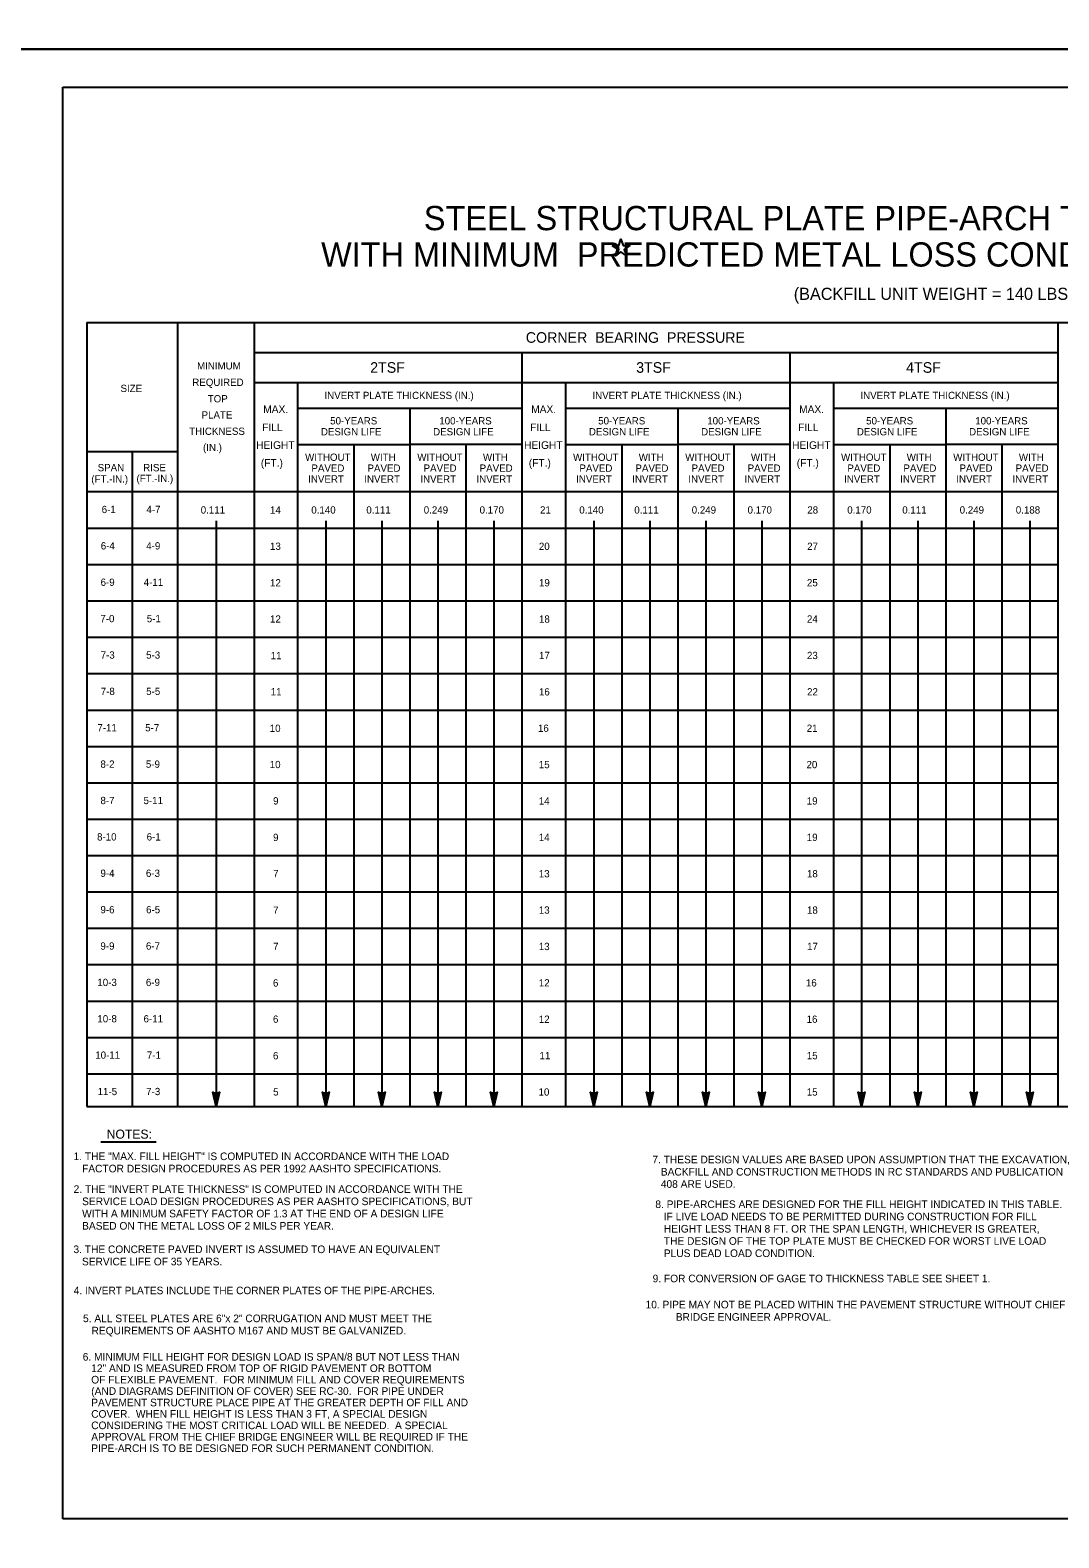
# Model space of a CAD drawing. Extents: x 591 to 2288, y -189 to 2187.
# Drawn here: x 1459 to 1865, y 1007 to 1601 of the extents above; entities that cross this region are included whole.
import ezdxf

# ---------------------------------------------------------------- set-up
doc = ezdxf.new("R2010")
doc.units = 0
for name, color, linetype in [('1', 7, 'Continuous'), ('2', 7, 'Continuous'), ('PLT-BNDY', 7, 'Continuous')]:
    doc.layers.add(name, color=color, linetype=linetype)

msp = doc.modelspace()

# ---------------------------------------------------------------- linework, layer by layer
at = {"layer": '1'}
for p, q in [((1481.73, 1485.59), (1481.73, 1176.64)), ((1481.73, 1485.59), (2247.72, 1485.59)), ((1517.56, 1485.59), (1517.56, 1176.64)), ((1547.65, 1485.59), (1547.65, 1176.64)), ((1864.37, 1485.59), (1864.37, 1176.64)), ((1547.65, 1473.72), (1864.37, 1473.72)), ((1653.22, 1473.72), (1653.22, 1176.64)), ((1758.8, 1473.72), (1758.8, 1176.64)), ((1547.65, 1461.85), (1653.22, 1461.85)), ((1564.84, 1461.85), (1564.84, 1176.64)), ((1653.22, 1461.85), (1758.8, 1461.85)), ((1670.41, 1461.85), (1670.41, 1176.64)), ((1758.8, 1461.85), (1864.37, 1461.85)), ((1775.98, 1461.85), (1775.98, 1176.64)), ((1564.84, 1451.82), (1653.22, 1451.82)), ((1609.03, 1451.82), (1609.03, 1176.64)), ((1670.41, 1451.82), (1758.8, 1451.82)), ((1714.6, 1451.82), (1714.6, 1176.64)), ((1775.98, 1451.82), (1864.37, 1451.82)), ((1820.17, 1451.82), (1820.17, 1176.64)), ((1564.84, 1437.48), (1609.03, 1437.48)), ((1586.94, 1437.48), (1586.94, 1176.64)), ((1653.22, 1437.48), (1609.03, 1437.48)), ((1631.13, 1437.48), (1631.13, 1176.64)), ((1670.41, 1437.48), (1714.6, 1437.48)), ((1692.51, 1437.48), (1692.51, 1176.64)), ((1758.8, 1437.48), (1714.6, 1437.48)), ((1736.7, 1437.48), (1736.7, 1176.64)), ((1775.98, 1437.48), (1820.17, 1437.48)), ((1798.08, 1437.48), (1798.08, 1176.64)), ((1864.37, 1437.48), (1820.17, 1437.48)), ((1842.27, 1437.48), (1842.27, 1176.64)), ((1517.56, 1434.62), (1481.73, 1434.62)), ((1499.64, 1434.62), (1499.64, 1176.64)), ((1864.37, 1418.85), (1481.73, 1418.85)), ((1481.73, 1404.52), (1864.37, 1404.52)), ((1532.75, 1407.43), (1532.75, 1176.64)), ((1575.88, 1407.43), (1575.88, 1176.64)), ((1597.99, 1407.43), (1597.99, 1176.64)), ((1620.08, 1407.43), (1620.08, 1176.64)), ((1642.18, 1407.43), (1642.18, 1176.64)), ((1681.46, 1407.43), (1681.46, 1176.64)), ((1703.56, 1407.43), (1703.56, 1176.64)), ((1725.65, 1407.43), (1725.65, 1176.64)), ((1747.75, 1407.43), (1747.75, 1176.64)), ((1787.03, 1407.43), (1787.03, 1176.64)), ((1809.13, 1407.43), (1809.13, 1176.64)), ((1831.22, 1407.43), (1831.22, 1176.64)), ((1853.32, 1407.43), (1853.32, 1176.64)), ((1481.73, 1390.19), (1864.37, 1390.19)), ((1481.73, 1375.86), (1864.37, 1375.86)), ((1481.73, 1361.52), (1864.37, 1361.52)), ((1481.73, 1347.19), (1864.37, 1347.19)), ((1481.73, 1332.86), (1864.37, 1332.86)), ((1481.73, 1318.53), (1864.37, 1318.53)), ((1481.73, 1304.2), (1864.37, 1304.2)), ((1481.73, 1289.86), (1864.37, 1289.86)), ((1481.73, 1275.53), (1864.37, 1275.53)), ((1481.73, 1261.2), (1864.37, 1261.2)), ((1481.73, 1246.87), (1864.37, 1246.87)), ((1481.73, 1232.54), (1864.37, 1232.54)), ((1481.73, 1218.2), (1864.37, 1218.2)), ((1481.73, 1203.87), (1864.37, 1203.87)), ((1481.73, 1189.54), (1864.37, 1189.54)), ((1481.73, 1176.64), (1864.37, 1176.64)), ((1864.37, 1176.64), (2247.72, 1176.64)), ((1487.31, 1162.71), (1509.1, 1162.71))]:
    msp.add_line(p, q, dxfattribs=at)
for points in [[(1533.72, 1182.06), (1533.16, 1181.86), (1532.75, 1176.64), (1533.72, 1182.06), (1534.07, 1182.34), (1532.75, 1176.64), (1532.37, 1181.86), (1531.81, 1182.05), (1532.75, 1176.64), (1531.44, 1182.34), (1531.81, 1182.05)], [(1576.86, 1182.06), (1576.3, 1181.86), (1575.88, 1176.64), (1576.86, 1182.06), (1577.21, 1182.34), (1575.88, 1176.64), (1575.51, 1181.86), (1574.95, 1182.05), (1575.88, 1176.64), (1574.58, 1182.34), (1574.95, 1182.05)], [(1598.97, 1182.06), (1598.4, 1181.86), (1597.99, 1176.64), (1598.97, 1182.06), (1599.31, 1182.34), (1597.99, 1176.64), (1597.61, 1181.86), (1597.05, 1182.05), (1597.99, 1176.64), (1596.68, 1182.34), (1597.05, 1182.05)], [(1621.06, 1182.06), (1620.5, 1181.86), (1620.08, 1176.64), (1621.06, 1182.06), (1621.4, 1182.34), (1620.08, 1176.64), (1619.71, 1181.86), (1619.15, 1182.05), (1620.08, 1176.64), (1618.78, 1182.34), (1619.15, 1182.05)], [(1643.16, 1182.06), (1642.59, 1181.86), (1642.18, 1176.64), (1643.16, 1182.06), (1643.5, 1182.34), (1642.18, 1176.64), (1641.81, 1181.86), (1641.25, 1182.05), (1642.18, 1176.64), (1640.87, 1182.34), (1641.25, 1182.05)], [(1682.44, 1182.06), (1681.87, 1181.86), (1681.46, 1176.64), (1682.44, 1182.06), (1682.78, 1182.34), (1681.46, 1176.64), (1681.08, 1181.86), (1680.53, 1182.05), (1681.46, 1176.64), (1680.15, 1182.34), (1680.53, 1182.05)], [(1704.54, 1182.06), (1703.97, 1181.86), (1703.56, 1176.64), (1704.54, 1182.06), (1704.88, 1182.34), (1703.56, 1176.64), (1703.18, 1181.86), (1702.62, 1182.05), (1703.56, 1176.64), (1702.25, 1182.34), (1702.62, 1182.05)], [(1726.63, 1182.06), (1726.07, 1181.86), (1725.65, 1176.64), (1726.63, 1182.06), (1726.97, 1182.34), (1725.65, 1176.64), (1725.28, 1181.86), (1724.72, 1182.05), (1725.65, 1176.64), (1724.35, 1182.34), (1724.72, 1182.05)], [(1748.73, 1182.06), (1748.17, 1181.86), (1747.75, 1176.64), (1748.73, 1182.06), (1749.07, 1182.34), (1747.75, 1176.64), (1747.38, 1181.86), (1746.82, 1182.05), (1747.75, 1176.64), (1746.45, 1182.34), (1746.82, 1182.05)], [(1788.01, 1182.06), (1787.44, 1181.86), (1787.03, 1176.64), (1788.01, 1182.06), (1788.35, 1182.34), (1787.03, 1176.64), (1786.65, 1181.86), (1786.1, 1182.05), (1787.03, 1176.64), (1785.72, 1182.34), (1786.1, 1182.05)], [(1810.11, 1182.06), (1809.54, 1181.86), (1809.13, 1176.64), (1810.11, 1182.06), (1810.45, 1182.34), (1809.13, 1176.64), (1808.76, 1181.86), (1808.19, 1182.05), (1809.13, 1176.64), (1807.82, 1182.34), (1808.19, 1182.05)], [(1832.2, 1182.06), (1831.64, 1181.86), (1831.22, 1176.64), (1832.2, 1182.06), (1832.55, 1182.34), (1831.22, 1176.64), (1830.85, 1181.86), (1830.29, 1182.05), (1831.22, 1176.64), (1829.92, 1182.34), (1830.29, 1182.05)], [(1854.3, 1182.06), (1853.74, 1181.86), (1853.32, 1176.64), (1854.3, 1182.06), (1854.64, 1182.34), (1853.32, 1176.64), (1852.95, 1181.86), (1852.39, 1182.05), (1853.32, 1176.64), (1852.02, 1182.34), (1852.39, 1182.05)]]:
    msp.add_lwpolyline(points, dxfattribs=at)
at = {"layer": '2'}
for p, q in [((1472.34, 1014.21), (1472.34, 1578.21)), ((1472.34, 1578.21), (2258.34, 1578.21)), ((1692.07, 1514.69), (1692.07, 1514.69)), ((2258.34, 1014.21), (1472.34, 1014.21))]:
    msp.add_line(p, q, dxfattribs=at)
msp.add_lwpolyline([(1688.77, 1515.92), (1691.41, 1515.89), (1692.22, 1518.42), (1693.02, 1515.89), (1695.67, 1515.92), (1693.51, 1514.35), (1694.35, 1511.85), (1692.2, 1513.41), (1690.09, 1511.85), (1690.9, 1514.36), (1688.77, 1515.92)], dxfattribs=at)
at = {"layer": 'PLT-BNDY'}
for points in [[(1432.34, 2187.21), (2273.34, 2187.21), (2273.34, 1593.21), (1432.34, 1593.21)], [(1432.34, 1593.21), (2273.34, 1593.21), (2273.34, 999.21), (1432.34, 999.21)]]:
    msp.add_lwpolyline(points, close=True, dxfattribs=at)

# ---------------------------------------------------------------- texts
at = {"layer": '1'}
for s, height, p in [('STEEL STRUCTURAL PLATE PIPE-ARCH THICKNESS REQUIREMENTS', 9.5546, (1614.55, 1521.89)), ('WITH MINIMUM  PREDICTED METAL LOSS CONDITION (18" CORNER RADIUS)', 9.5546, (1574.08, 1507.57)), ('(BACKFILL UNIT WEIGHT = 140 LBS. PER CU. FT.)', 4.7773, (1760.29, 1494.45)), ('CORNER  BEARING  PRESSURE', 4.1801, (1654.73, 1477.53)), ('MINIMUM', 2.866, (1525.2, 1467.03)), ('2TSF', 4.18, (1593.42, 1465.72)), ('3TSF', 4.18, (1698.21, 1465.72)), ('4TSF', 4.18, (1804.57, 1465.72)), ('REQUIRED', 2.866, (1523.33, 1460.55)), ('SIZE', 2.866, (1495.05, 1458.15)), ('TOP', 2.866, (1529.42, 1454.07)), ('INVERT PLATE THICKNESS (IN.)', 2.8664, (1575.41, 1455.37)), ('INVERT PLATE THICKNESS (IN.)', 2.8664, (1680.98, 1455.37)), ('INVERT PLATE THICKNESS (IN.)', 2.8664, (1786.55, 1455.37)), ('PLATE', 2.866, (1526.99, 1447.67)), ('THICKNESS', 2.866, (1522.12, 1441.26)), ('DESIGN LIFE', 2.8664, (1574.01, 1441.07)), ('50-YEARS', 2.866, (1577.66, 1445.37)), ('DESIGN LIFE', 2.8664, (1618.21, 1441.07)), ('100-YEARS', 2.866, (1620.64, 1445.37)), ('DESIGN LIFE', 2.8664, (1679.58, 1441.07)), ('50-YEARS', 2.866, (1683.24, 1445.37)), ('DESIGN LIFE', 2.8664, (1723.78, 1441.07)), ('100-YEARS', 2.866, (1726.21, 1445.37)), ('DESIGN LIFE', 2.8664, (1785.15, 1441.07)), ('50-YEARS', 2.866, (1788.81, 1445.37)), ('DESIGN LIFE', 2.8664, (1829.35, 1441.07)), ('100-YEARS', 2.866, (1831.78, 1445.37)), ('(IN.)', 2.866, (1527.56, 1434.86)), ('WITHOUT', 2.866, (1567.78, 1431.03)), ('WITH', 2.866, (1593.65, 1431.03)), ('WITHOUT', 2.866, (1611.97, 1431.03)), ('WITH', 2.866, (1637.84, 1431.03)), ('WITHOUT', 2.866, (1673.35, 1431.03)), ('WITH', 2.866, (1699.22, 1431.03)), ('WITHOUT', 2.866, (1717.54, 1431.03)), ('WITH', 2.866, (1743.41, 1431.03)), ('WITHOUT', 2.866, (1778.92, 1431.03)), ('WITH', 2.866, (1804.79, 1431.03)), ('WITHOUT', 2.866, (1823.11, 1431.03)), ('WITH', 2.866, (1848.98, 1431.03)), ('SPAN', 2.866, (1486.06, 1426.92)), ('(FT.-IN.)', 2.866, (1501.35, 1422.65)), ('RISE', 2.866, (1503.99, 1426.92)), ('PAVED', 2.866, (1570.27, 1426.73)), ('PAVED', 2.866, (1592.36, 1426.73)), ('PAVED', 2.866, (1614.46, 1426.73)), ('PAVED', 2.866, (1636.55, 1426.73)), ('PAVED', 2.866, (1675.84, 1426.73)), ('PAVED', 2.866, (1697.93, 1426.73)), ('PAVED', 2.866, (1720.03, 1426.73)), ('PAVED', 2.866, (1742.12, 1426.73)), ('PAVED', 2.866, (1781.41, 1426.73)), ('PAVED', 2.866, (1803.5, 1426.73)), ('PAVED', 2.866, (1825.6, 1426.73)), ('PAVED', 2.866, (1847.7, 1426.73)), ('(FT.-IN.)', 2.866, (1483.55, 1422.45)), ('INVERT', 2.866, (1569, 1422.44)), ('INVERT', 2.866, (1591.09, 1422.44)), ('INVERT', 2.866, (1613.19, 1422.44)), ('INVERT', 2.866, (1635.29, 1422.44)), ('INVERT', 2.866, (1674.57, 1422.44)), ('INVERT', 2.866, (1696.66, 1422.44)), ('INVERT', 2.866, (1718.76, 1422.44)), ('INVERT', 2.866, (1740.86, 1422.44)), ('INVERT', 2.866, (1780.14, 1422.44)), ('INVERT', 2.866, (1802.23, 1422.44)), ('INVERT', 2.866, (1824.33, 1422.44)), ('INVERT', 2.866, (1846.43, 1422.44)), ('6-1', 2.866, (1487.63, 1410.44)), ('4-7', 2.866, (1505.26, 1410.44)), ('0.111', 2.866, (1526.66, 1410.25)), ('14', 2.866, (1553.95, 1410.21)), ('0.140', 2.866, (1570.22, 1410.25)), ('0.111', 2.866, (1591.9, 1410.25)), ('0.249', 2.866, (1614.52, 1410.25)), ('0.170', 2.866, (1636.52, 1410.25)), ('21', 2.866, (1660.33, 1410.25)), ('0.140', 2.866, (1675.79, 1410.25)), ('0.111', 2.866, (1697.47, 1410.25)), ('0.249', 2.866, (1720.09, 1410.25)), ('0.170', 2.866, (1742.09, 1410.25)), ('28', 2.866, (1765.62, 1410.25)), ('0.170', 2.866, (1781.36, 1410.25)), ('0.111', 2.866, (1803.04, 1410.25)), ('0.249', 2.866, (1825.66, 1410.25)), ('0.188', 2.866, (1847.77, 1410.25)), ('6-4', 2.866, (1487.28, 1396.11)), ('4-9', 2.866, (1505.19, 1396.11)), ('13', 2.866, (1553.95, 1395.96)), ('20', 2.866, (1659.88, 1395.92)), ('27', 2.866, (1765.56, 1395.92)), ('6-9', 2.866, (1487.21, 1381.77)), ('4-11', 2.866, (1504.19, 1381.77)), ('12', 2.866, (1553.95, 1381.55)), ('19', 2.866, (1659.91, 1381.59)), ('25', 2.866, (1765.49, 1381.59)), ('7-0', 2.866, (1487.11, 1367.44)), ('5-1', 2.866, (1505.41, 1367.44)), ('12', 2.866, (1553.95, 1367.29)), ('18', 2.866, (1659.92, 1367.26)), ('24', 2.866, (1765.49, 1367.26)), ('7-3', 2.866, (1487.22, 1353.11)), ('5-3', 2.866, (1505.14, 1353.11)), ('11', 2.866, (1554.23, 1352.89)), ('17', 2.866, (1659.93, 1352.92)), ('23', 2.866, (1765.5, 1352.92)), ('7-8', 2.866, (1487.25, 1338.78)), ('5-5', 2.866, (1505.17, 1338.78)), ('11', 2.866, (1554.23, 1338.63)), ('16', 2.866, (1659.89, 1338.59)), ('22', 2.866, (1765.53, 1338.59)), ('7-11', 2.866, (1485.93, 1324.45)), ('5-7', 2.866, (1504.78, 1324.45)), ('10', 2.866, (1553.85, 1324.22)), ('16', 2.866, (1659.5, 1324.26)), ('21', 2.866, (1765.42, 1324.26)), ('8-2', 2.866, (1487.15, 1310.11)), ('5-9', 2.866, (1505.05, 1310.11)), ('10', 2.866, (1553.85, 1309.96)), ('15', 2.866, (1659.85, 1309.93)), ('20', 2.866, (1765.31, 1309.93)), ('8-7', 2.866, (1487.15, 1295.78)), ('5-11', 2.866, (1504.12, 1295.78)), ('9', 2.87, (1555.16, 1295.63)), ('14', 2.866, (1659.85, 1295.6)), ('19', 2.866, (1765.41, 1295.6)), ('8-10', 2.866, (1485.82, 1281.45)), ('6-1', 2.866, (1505.34, 1281.45)), ('9', 2.87, (1555.16, 1281.23)), ('14', 2.866, (1659.85, 1281.27)), ('19', 2.866, (1765.41, 1281.27)), ('9-4', 2.866, (1487.15, 1267.12)), ('6-3', 2.866, (1505.06, 1267.12)), ('7', 2.87, (1555.17, 1266.97)), ('13', 2.866, (1659.85, 1266.93)), ('18', 2.866, (1765.49, 1266.93)), ('9-6', 2.866, (1487.15, 1252.79)), ('6-5', 2.866, (1505.13, 1252.79)), ('7', 2.87, (1555.17, 1252.56)), ('13', 2.866, (1659.85, 1252.6)), ('18', 2.866, (1765.5, 1252.6)), ('9-9', 2.866, (1487.13, 1238.45)), ('6-7', 2.866, (1505.06, 1238.45)), ('7', 2.87, (1555.17, 1238.3)), ('13', 2.866, (1659.85, 1238.27)), ('17', 2.866, (1765.53, 1238.27)), ('10-3', 2.866, (1485.93, 1224.12)), ('6-9', 2.866, (1505.05, 1224.12)), ('6', 2.87, (1555.11, 1223.9)), ('12', 2.866, (1659.85, 1223.94)), ('16', 2.866, (1765.07, 1223.94)), ('10-8', 2.866, (1485.94, 1209.79)), ('6-11', 2.866, (1504.13, 1209.79)), ('6', 2.87, (1555.11, 1209.64)), ('12', 2.866, (1659.85, 1209.61)), ('16', 2.866, (1765.35, 1209.61)), ('10-11', 2.866, (1485.1, 1195.46)), ('7-1', 2.866, (1505.45, 1195.46)), ('6', 2.87, (1555.11, 1195.23)), ('11', 2.866, (1660.13, 1195.27)), ('15', 2.866, (1765.42, 1195.27)), ('11-5', 2.866, (1486.04, 1181.13)), ('7-3', 2.866, (1505.17, 1181.13)), ('5', 2.87, (1555.18, 1180.98)), ('10', 2.866, (1659.74, 1180.94)), ('15', 2.866, (1765.42, 1180.94)), ('NOTES:', 3.583, (1489.6, 1163.97)), ('  1. THE "MAX. FILL HEIGHT" IS COMPUTED IN ACCORDANCE WITH THE LOAD ', 3, (1474.34, 1155.53)), ('     FACTOR DESIGN PROCEDURES AS PER 1992 AASHTO SPECIFICATIONS.', 3, (1474.34, 1150.71)), ('7. THESE DESIGN VALUES ARE BASED UPON ASSUMPTION THAT THE EXCAVATION,', 3, (1704.58, 1154.26)), ('   BACKFILL AND CONSTRUCTION METHODS IN RC STANDARDS AND PUBLICATION', 3, (1704.58, 1149.44)), ('   408 ARE USED.', 3, (1704.58, 1144.61)), ('  2. THE "INVERT PLATE THICKNESS" IS COMPUTED IN ACCORDANCE WITH THE', 3, (1474.35, 1142.61)), ('     SERVICE LOAD DESIGN PROCEDURES AS PER AASHTO SPECIFICATIONS, BUT ', 3, (1474.35, 1137.79)), ('     WITH A MINIMUM SAFETY FACTOR OF 1.3 AT THE END OF A DESIGN LIFE ', 3, (1474.35, 1132.96)), ('8. PIPE-ARCHES ARE DESIGNED FOR THE FILL HEIGHT INDICATED IN THIS TABLE.', 3, (1705.76, 1136.64)), ('   IF LIVE LOAD NEEDS TO BE PERMITTED DURING CONSTRUCTION FOR FILL', 3, (1705.76, 1131.82)), ('     BASED ON THE METAL LOSS OF 2 MILS PER YEAR.', 3, (1474.35, 1128.14)), ('   HEIGHT LESS THAN 8 FT. OR THE SPAN LENGTH, WHICHEVER IS GREATER,', 3, (1705.76, 1126.99)), ('   THE DESIGN OF THE TOP PLATE MUST BE CHECKED FOR WORST LIVE LOAD', 3, (1705.76, 1122.17)), ('  3. THE CONCRETE PAVED INVERT IS ASSUMED TO HAVE AN EQUIVALENT', 3, (1474.29, 1118.89)), ('     SERVICE LIFE OF 35 YEARS.', 3, (1474.29, 1114.07)), ('   PLUS DEAD LOAD CONDITION.', 3, (1705.76, 1117.35)), ('9. FOR CONVERSION OF GAGE TO THICKNESS TABLE SEE SHEET 1.', 3, (1704.69, 1107.39)), ('5. ALL STEEL PLATES ARE 6"x 2" CORRUGATION AND MUST MEET THE', 3, (1480.29, 1091.68)), ('   REQUIREMENTS OF AASHTO M167 AND MUST BE GALVANIZED.', 3, (1480.29, 1086.85))]:
    msp.add_text(s, height=height, dxfattribs=at).set_placement(p)
at = {"layer": '2'}
for s, height, p in [('MAX.', 3, (1551.28, 1449.86)), ('MAX.', 3, (1656.85, 1449.86)), ('MAX.', 3, (1762.42, 1449.86)), ('FILL', 3, (1550.86, 1442.73)), ('FILL', 3, (1656.43, 1442.73)), ('FILL', 3, (1762, 1442.73)), ('HEIGHT', 3, (1548.46, 1435.73)), ('HEIGHT', 3, (1654.03, 1435.73)), ('HEIGHT', 3, (1759.61, 1435.73)), ('(FT.)', 3, (1550.33, 1428.73)), ('(FT.)', 3, (1655.9, 1428.73)), ('(FT.)', 3, (1761.47, 1428.73)), ('  4. INVERT PLATES INCLUDE THE CORNER PLATES OF THE PIPE-ARCHES.', 2.97, (1474.41, 1102.69)), ('10. PIPE MAY NOT BE PLACED WITHIN THE PAVEMENT STRUCTURE WITHOUT CHIEF', 3, (1701.9, 1097.11)), ('BRIDGE ENGINEER APPROVAL.', 3, (1713.81, 1092.24)), ('6. MINIMUM FILL HEIGHT FOR DESIGN LOAD IS SPAN/8 BUT NOT LESS THAN', 3, (1480.17, 1076.53)), ('   OF FLEXIBLE PAVEMENT.  FOR MINIMUM FILL AND COVER REQUIREMENTS ', 3, (1480.17, 1067.53)), ('   12" AND IS MEASURED FROM TOP OF RIGID PAVEMENT OR BOTTOM', 3, (1480.17, 1072.03)), ('   (AND DIAGRAMS DEFINITION OF COVER) SEE RC-30.  FOR PIPE UNDER', 3, (1480.17, 1063.03)), ('   PAVEMENT STRUCTURE PLACE PIPE AT THE GREATER DEPTH OF FILL AND', 3, (1480.17, 1058.53)), ('   COVER.  WHEN FILL HEIGHT IS LESS THAN 3 FT, A SPECIAL DESIGN', 3, (1480.17, 1054.03)), ('   CONSIDERING THE MOST CRITICAL LOAD WILL BE NEEDED.  A SPECIAL', 3, (1480.17, 1049.53)), ('   APPROVAL FROM THE CHIEF BRIDGE ENGINEER WILL BE REQUIRED IF THE', 3, (1480.17, 1045.03)), ('   PIPE-ARCH IS TO BE DESIGNED FOR SUCH PERMANENT CONDITION.', 3, (1480.17, 1040.53))]:
    msp.add_text(s, height=height, dxfattribs=at).set_placement(p)

doc.saveas('drawing.dxf')
